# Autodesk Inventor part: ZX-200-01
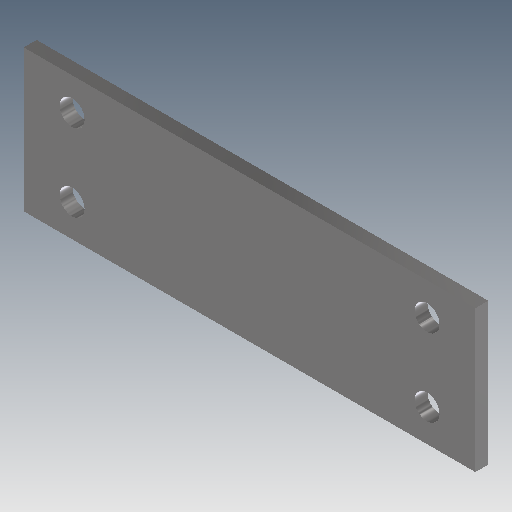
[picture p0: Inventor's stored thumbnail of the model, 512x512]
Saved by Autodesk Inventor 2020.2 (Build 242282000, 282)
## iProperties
Created: 2015-11
Part Number: ZX-200-01
Material: Stal, miękka
Document SubType Name: Modelowanie
Designer: F.Stasiak
Density: 7.85 g/cm^3
Appearance: Częściowo polerowany
Mass: 2928.47 g
Surface Area: 862.613 cm^2
Volume: 373.054 cm^3
Sheet Metal Rule: Domyślny_mm
Catalog Web Link: www.expertbooks.pl
Manager: www.cadconsulting.pl
Company: Fabian Stasiak CAD Consulting
Author: F.Stasiak
Subject: Zbiór ćwiczeń. Autodesk Inventor 2020. Kurs Professional
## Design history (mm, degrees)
node "Powierzchnia1"
  sketch "Szkic1"
    geometry: L1 (-175, 55)-(175, 55); L2 (175, 55)-(175, -55); L3 (175, -55)-(-175, -55); L4 (-175, -55)-(-175, 55); L5 (-175, 55)-(175, -55); L6 (175, 55)-(-175, -55); 1 further point
    constraints: 12 end point, 2 midpoint, 2 parallel, 1 horizontal, 1 perpendicular
    dimensions: "d0" = 350 distance of L2.end L3.end; "d1" = 110 distance of L1.end L2.end
sketch "Szkic4"
  geometry: L1 (137.5, 30)-(-137.5, 30); L2 (-137.5, 30)-(-137.5, -30); L3 (-137.5, -30)-(137.5, -30); L4 (137.5, -30)-(137.5, 30); L5 (137.5, 30)-(-137.5, -30); L6 (-137.5, 30)-(137.5, -30); 1 further point
  constraints: 12 end point, 2 midpoint, 2 parallel, 1 horizontal, 1 perpendicular
  dimensions: "d23" = 275 distance of L3.end L2.end; "d24" = 60 distance of L2.end L1.end
hole "Otwór2" sketch "Szkic4" at (-137.5, 30), (-137.5, -30), (137.5, 30), (137.5, -30) diameter "d25" = 19.5; stored, may be unused: countersink angle "d29" = 90 deg, drill point angle "d31" = 118 deg; dims "d26" = 6, "d27" = 4, "d28" = 2, "d30" = 8
node "Bryła1"
feature "Płyta1" dims "d32" = 10 (= Grubość)
other parameters: "Grubość" = 10, "WspółczynnikK" = 4.4, "GłębokośćGięciaPodcięcia" = 5 (= 0.5 x Grubość), "OdstępPołączenia" = 0.01
